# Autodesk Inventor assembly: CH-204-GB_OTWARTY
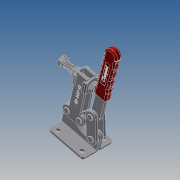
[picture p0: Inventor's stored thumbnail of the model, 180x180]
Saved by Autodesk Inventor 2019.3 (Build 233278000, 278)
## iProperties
Company: ·L?¤¤?
Created: 2010-06
Part Number: CH-204-GB_OTWARTY
Material: Ogólny
Description: STEP AP203
Document SubType Name: Assembly
Designer: CADENGINEERING4
Sending System: SolidWorks 2005179
Preprocessor: SwSTEP 2.0
Title: CH-204-GB.STEP
Author: ·L?¥Î?
Revision Number: ANY
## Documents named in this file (12)
- E:\STRONA\Horizontal toggle clamp\CH-204-GB\CH-204-GB_OTWARTY.iam
- E:\STRONA\Horizontal toggle clamp\CH-204-GB\204-GB-06___.ipt
- E:\STRONA\Horizontal toggle clamp\CH-204-GB\CH-FC-12300-01___.ipt
- E:\STRONA\Horizontal toggle clamp\CH-204-GB\204-GB-05___.ipt
- E:\STRONA\Horizontal toggle clamp\CH-204-GB\204-GB-01___.ipt
- E:\STRONA\Horizontal toggle clamp\CH-204-GB\204-GB-08___.ipt
- E:\STRONA\Horizontal toggle clamp\CH-204-GB\FW120(2)___.ipt
- E:\STRONA\Horizontal toggle clamp\CH-204-GB\204-GB-04___.ipt
- E:\STRONA\Horizontal toggle clamp\CH-204-GB\204-GB-02___.ipt
- E:\STRONA\Horizontal toggle clamp\CH-204-GB\204-GB-07___.ipt
- E:\STRONA\Horizontal toggle clamp\CH-204-GB\204-GB-03___.ipt
- E:\STRONA\Horizontal toggle clamp\CH-204-GB\CH-FC-12130___.ipt
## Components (23 placed, 23 different names)
1. 204-GB-06_??_1 — Zestawiające:30, Zestawiające:32
2. CH-FC-12300-01_??_2 — Równoległe:3, Zestawiające:3, Zestawiające:4
3. 204-GB-05_??_3 — Zestawiające:39, Zestawiające:41
4. 204-GB-01_??_4 — Zestawiające:19, Zestawiające:20, Zestawiające:21, Zestawiające:22, Zestawiające:23, Zestawiające:38, Zestawiające:39, Zestawiające:40, Zestawiające:41, Zestawiające:43, Kątowe:1
5. 204-GB-08_??_5 — Zestawiające:17, Zestawiające:18, Zestawiające:47
6. FW120(2)_??_6 — Równoległe:2, Zestawiające:2, Zestawiające:6, Zestawiające:7
7. 204-GB-05_??_7 — Zestawiające:20, Zestawiające:21, Zestawiające:24
8. 204-GB-06_??_8 — Zestawiające:13, Zestawiające:16
9. 204-GB-04_??_9 — Zestawiające:27, Zestawiające:28, Zestawiające:29, Zestawiające:30, Zestawiające:32
10. FW120(2)_??_10 — Równoległe:1, Równoległe:2, Zestawiające:1, Zestawiające:4, Zestawiające:8
11. 204-GB-06_??_11 — Zestawiające:14, Zestawiające:15, Zestawiające:46
12. 204-GB-05_??_12 — Zestawiające:19, Zestawiające:22, Zestawiające:27
13. 204-GB-08_??_13 — Zestawiające:23, Zestawiające:25, Zestawiające:26, Zestawiające:28
14. 204-GB-02_??_14 — Równoległe:1, Zestawiające:7, Zestawiające:8, Zestawiające:9, Zestawiające:13, Zestawiające:14, Zestawiające:15, Zestawiające:16, Zestawiające:17, Zestawiające:18, Zestawiające:42, Zestawiające:43, Zestawiające:44, Zestawiające:45
15. 204-GB-06_??_15 — Zestawiające:31, Zestawiające:33, Zestawiające:36
16. 204-GB-08_??_16 — Zestawiające:44, Zestawiające:45
17. 204-GB-07_??_17 — Zestawiające:10, Zestawiające:11, Zestawiające:12
18. 204-GB-03_??_18 — Zestawiające:10, Zestawiające:11, Zestawiające:12, Zestawiające:36, Zestawiające:37, Zestawiające:46, Zestawiające:47, Kątowe:1
19. 204-GB-08_??_19 — Zestawiające:34, Zestawiające:35, Zestawiające:37
20. 204-GB-05_??_20 — Zestawiające:38, Zestawiające:40, Zestawiające:42
21. CH-FC-12130_??_21 — Równoległe:3, Zestawiające:1, Zestawiające:2, Zestawiające:3, Zestawiające:5, Zestawiające:9
22. CH-FC-12300-01_??_22 — Zestawiające:5, Zestawiające:6
23. 204-GB-04_??_23 — Zestawiające:24, Zestawiające:25, Zestawiające:26, Zestawiające:29, Zestawiające:31, Zestawiające:33, Zestawiające:34, Zestawiające:35
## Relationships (51: Mate 47, Flush 3, Angle 1)
- Równoległe:1 [Flush]: FW120(2)_??_10 ↔ 204-GB-02_??_14
- Równoległe:2 [Flush]: FW120(2)_??_6 ↔ FW120(2)_??_10
- Równoległe:3 [Flush]: CH-FC-12300-01_??_2 ↔ CH-FC-12130_??_21
- Zestawiające:1 [Mate]: FW120(2)_??_10 ↔ CH-FC-12130_??_21
- Zestawiające:2 [Mate]: FW120(2)_??_6 ↔ CH-FC-12130_??_21
- Zestawiające:3 [Mate]: CH-FC-12300-01_??_2 ↔ CH-FC-12130_??_21
- Zestawiające:4 [Mate]: CH-FC-12300-01_??_2 ↔ FW120(2)_??_10
- Zestawiające:5 [Mate]: CH-FC-12130_??_21 ↔ CH-FC-12300-01_??_22
- Zestawiające:6 [Mate]: FW120(2)_??_6 ↔ CH-FC-12300-01_??_22
- Zestawiające:7 [Mate]: FW120(2)_??_6 ↔ 204-GB-02_??_14
- Zestawiające:8 [Mate]: FW120(2)_??_10 ↔ 204-GB-02_??_14
- Zestawiające:9 [Mate]: 204-GB-02_??_14 ↔ CH-FC-12130_??_21
- Zestawiające:10 [Mate]: 204-GB-07_??_17 ↔ 204-GB-03_??_18
- Zestawiające:11 [Mate]: 204-GB-07_??_17 ↔ 204-GB-03_??_18
- Zestawiające:12 [Mate]: 204-GB-07_??_17 ↔ 204-GB-03_??_18
- Zestawiające:13 [Mate]: 204-GB-06_??_8 ↔ 204-GB-02_??_14
- Zestawiające:14 [Mate]: 204-GB-06_??_11 ↔ 204-GB-02_??_14
- Zestawiające:15 [Mate]: 204-GB-06_??_11 ↔ 204-GB-02_??_14
- Zestawiające:16 [Mate]: 204-GB-06_??_8 ↔ 204-GB-02_??_14
- Zestawiające:17 [Mate]: 204-GB-08_??_5 ↔ 204-GB-02_??_14
- Zestawiające:18 [Mate]: 204-GB-08_??_5 ↔ 204-GB-02_??_14
- Zestawiające:19 [Mate]: 204-GB-01_??_4 ↔ 204-GB-05_??_12
- Zestawiające:20 [Mate]: 204-GB-01_??_4 ↔ 204-GB-05_??_7
- Zestawiające:21 [Mate]: 204-GB-01_??_4 ↔ 204-GB-05_??_7
- Zestawiające:22 [Mate]: 204-GB-01_??_4 ↔ 204-GB-05_??_12
- Zestawiające:23 [Mate]: 204-GB-01_??_4 ↔ 204-GB-08_??_13
- Zestawiające:24 [Mate]: 204-GB-05_??_7 ↔ 204-GB-04_??_23
- Zestawiające:25 [Mate]: 204-GB-08_??_13 ↔ 204-GB-04_??_23
- Zestawiające:26 [Mate]: 204-GB-08_??_13 ↔ 204-GB-04_??_23
- Zestawiające:27 [Mate]: 204-GB-04_??_9 ↔ 204-GB-05_??_12
- Zestawiające:28 [Mate]: 204-GB-04_??_9 ↔ 204-GB-08_??_13
- Zestawiające:29 [Mate]: 204-GB-04_??_9 ↔ 204-GB-04_??_23
- Zestawiające:30 [Mate]: 204-GB-06_??_1 ↔ 204-GB-04_??_9
- Zestawiające:31 [Mate]: 204-GB-06_??_15 ↔ 204-GB-04_??_23
- Zestawiające:32 [Mate]: 204-GB-06_??_1 ↔ 204-GB-04_??_9
- Zestawiające:33 [Mate]: 204-GB-06_??_15 ↔ 204-GB-04_??_23
- Zestawiające:34 [Mate]: 204-GB-08_??_19 ↔ 204-GB-04_??_23
- Zestawiające:35 [Mate]: 204-GB-08_??_19 ↔ 204-GB-04_??_23
- Zestawiające:36 [Mate]: 204-GB-06_??_15 ↔ 204-GB-03_??_18
- Zestawiające:37 [Mate]: 204-GB-03_??_18 ↔ 204-GB-08_??_19
- Zestawiające:38 [Mate]: 204-GB-01_??_4 ↔ 204-GB-05_??_20
- Zestawiające:39 [Mate]: 204-GB-05_??_3 ↔ 204-GB-01_??_4
- Zestawiające:40 [Mate]: 204-GB-01_??_4 ↔ 204-GB-05_??_20
- Zestawiające:41 [Mate]: 204-GB-05_??_3 ↔ 204-GB-01_??_4
- Zestawiające:42 [Mate]: 204-GB-02_??_14 ↔ 204-GB-05_??_20
- Zestawiające:43 [Mate]: 204-GB-01_??_4 ↔ 204-GB-02_??_14
- Zestawiające:44 [Mate]: 204-GB-02_??_14 ↔ 204-GB-08_??_16
- Zestawiające:45 [Mate]: 204-GB-02_??_14 ↔ 204-GB-08_??_16
- Zestawiające:46 [Mate]: 204-GB-06_??_11 ↔ 204-GB-03_??_18
- Zestawiające:47 [Mate]: 204-GB-08_??_5 ↔ 204-GB-03_??_18
- Kątowe:1 [Angle]: 204-GB-01_??_4 ↔ 204-GB-03_??_18
